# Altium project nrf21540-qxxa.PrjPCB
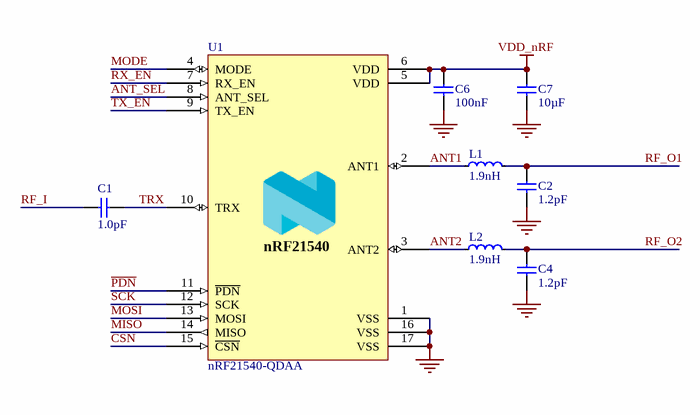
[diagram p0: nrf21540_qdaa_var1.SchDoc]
2 sheets, 18 parts. Net scope: global (net labels, ports and power ports of the same name join across sheets).
Board files: nrf21540_qdaa_var1.PcbDoc, nrf21540_qdaa_var2.PcbDoc
Sheets:
  nrf21540_qdaa_var1.SchDoc
  nrf21540_qdaa_var2.SchDoc

## Sheet nrf21540_qdaa_var1.SchDoc: nRF21540 Reference Layout Alt. 1
size A4; Revision: 0.7; SheetNumber: 1; SheetTotal: 1; DrawnBy: RUBR; DocumentSize: A4; PCAName: nRF21540 Reference Layout Alt. 1

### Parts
(Parts that share a designator on the sheet are numbered #1, #2 ... from top to bottom, then left to right.)
C1#1  1.0pF  [CAPC0603X03L_C]
C2#1  1.2pF  [CAPC0603X03L_C]
C4#1  1.2pF  [CAPC0603X03L_C]
C6#1  100nF  [CAPC0603X03L_C]
C7#1  10µF  [CAPC1608X06L]
L1#1  1.9nH  [INDC0603X03L_C]
L2#1  1.9nH  [INDC0603X03L_C]
U1#1  nRF21540-QDAA  [QFN65P400X400X65_HS-17N]

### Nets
GND: C2#1.1 C4#1.1 C6#1.1 C7#1.1 U1#1.1(VSS) U1#1.16(VSS) U1#1.17(VSS)
VDD_nRF: C6#1.2 C7#1.2 U1#1.5(VDD) U1#1.6(VDD)
ANT1: L1#1.1 U1#1.2(ANT1)
ANT2: L2#1.1 U1#1.3(ANT2)
ANT_SEL: U1#1.8(ANT_SEL)
~{CSN}: U1#1.15(~{CSN})
MISO: U1#1.14(MISO)
MODE: U1#1.4(MODE)
MOSI: U1#1.13(MOSI)
~{PDN}: U1#1.11(~{PDN})
RF_I: C1#1.1
RF_O1: C2#1.2 L1#1.2
RF_O2: C4#1.2 L2#1.2
RX_EN: U1#1.7(RX_EN)
SCK: U1#1.12(SCK)
TRX: C1#1.2 U1#1.10(TRX)
TX_EN: U1#1.9(TX_EN)

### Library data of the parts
C1#1 = C0201-1.0p: Capacitor, NP0, ±5%
C2#1 C4#1 = C0201-1.2p: Capacitor, NP0, ±5%
C6#1 = C0201-100n: Capacitor, X7S, ±10%
C7#1 = C0603-10µ: Capacitor, X7S, ±20%
L1#1 L2#1 = L0201-1n0: High frequency chip inductor ±5%; Part Number: L0201-1n9
U1#1 = nRF21540-QDAA: Radio front-end / range extender for 2.4GHz

## Sheet nrf21540_qdaa_var2.SchDoc: nRF21540 Reference Layout Alt. 2
size A4; Revision: 0.7; SheetNumber: 1; SheetTotal: 1; DrawnBy: RUBR; DocumentSize: A4; PCAName: nRF21540 Reference Layout Alt. 2
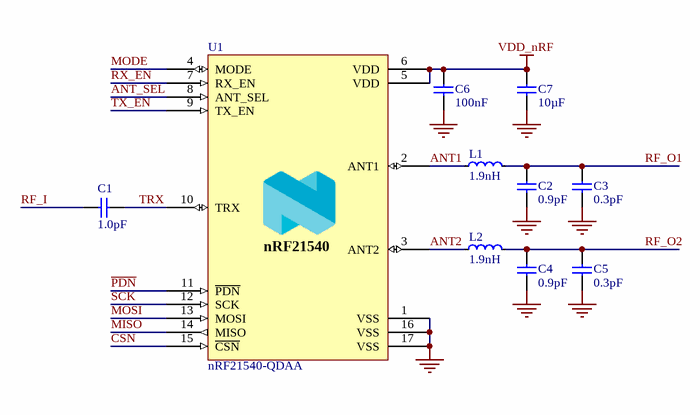
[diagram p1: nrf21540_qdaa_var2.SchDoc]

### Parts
(Parts that share a designator on the sheet are numbered #1, #2 ... from top to bottom, then left to right.)
C1#2  1.0pF  [CAPC0603X03L_C]
C2#2  0.9pF  [CAPC0603X03L_C]
C3  0.3pF  [CAPC0603X03L_C]
C4#2  0.9pF  [CAPC0603X03L_C]
C5  0.3pF  [CAPC0603X03L_C]
C6#2  100nF  [CAPC0603X03L_C]
C7#2  10µF  [CAPC1608X06L]
L1#2  1.9nH  [INDC0603X03L_C]
L2#2  1.9nH  [INDC0603X03L_C]
U1#2  nRF21540-QDAA  [QFN65P400X400X65_HS-17N]

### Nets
GND: C2#2.1 C3.1 C4#2.1 C5.1 C6#2.1 C7#2.1 U1#2.1(VSS) U1#2.16(VSS) U1#2.17(VSS)
VDD_nRF: C6#2.2 C7#2.2 U1#2.5(VDD) U1#2.6(VDD)
ANT1: L1#2.1 U1#2.2(ANT1)
ANT2: L2#2.1 U1#2.3(ANT2)
ANT_SEL: U1#2.8(ANT_SEL)
~{CSN}: U1#2.15(~{CSN})
MISO: U1#2.14(MISO)
MODE: U1#2.4(MODE)
MOSI: U1#2.13(MOSI)
~{PDN}: U1#2.11(~{PDN})
RF_I: C1#2.1
RF_O1: C2#2.2 C3.2 L1#2.2
RF_O2: C4#2.2 C5.2 L2#2.2
RX_EN: U1#2.7(RX_EN)
SCK: U1#2.12(SCK)
TRX: C1#2.2 U1#2.10(TRX)
TX_EN: U1#2.9(TX_EN)

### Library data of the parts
C1#2 = C0201-1.0p: Capacitor, NP0, ±5%
C2#2 C4#2 = C0201-0.9p: Capacitor, NP0, ±5%
C3 C5 = C0201-0.3p: Capacitor, NP0, ±5%
C6#2 = C0201-100n: Capacitor, X7S, ±10%
C7#2 = C0603-10µ: Capacitor, X7S, ±20%
L1#2 L2#2 = L0201-1n0: as L1#1 on sheet nrf21540_qdaa_var1
U1#2 = nRF21540-QDAA: as U1#1 on sheet nrf21540_qdaa_var1

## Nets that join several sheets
GND: nrf21540_qdaa_var1 (7 pins), nrf21540_qdaa_var2 (9 pins)
VDD_nRF: nrf21540_qdaa_var1 (C6#1.2 C7#1.2 U1#1.5 U1#1.6), nrf21540_qdaa_var2 (C6#2.2 C7#2.2 U1#2.5 U1#2.6)
ANT1: nrf21540_qdaa_var1 (L1#1.1 U1#1.2), nrf21540_qdaa_var2 (L1#2.1 U1#2.2)
ANT2: nrf21540_qdaa_var1 (L2#1.1 U1#1.3), nrf21540_qdaa_var2 (L2#2.1 U1#2.3)
ANT_SEL: nrf21540_qdaa_var1 (U1#1.8), nrf21540_qdaa_var2 (U1#2.8)
~{CSN}: nrf21540_qdaa_var1 (U1#1.15), nrf21540_qdaa_var2 (U1#2.15)
MISO: nrf21540_qdaa_var1 (U1#1.14), nrf21540_qdaa_var2 (U1#2.14)
MODE: nrf21540_qdaa_var1 (U1#1.4), nrf21540_qdaa_var2 (U1#2.4)
MOSI: nrf21540_qdaa_var1 (U1#1.13), nrf21540_qdaa_var2 (U1#2.13)
~{PDN}: nrf21540_qdaa_var1 (U1#1.11), nrf21540_qdaa_var2 (U1#2.11)
RF_I: nrf21540_qdaa_var1 (C1#1.1), nrf21540_qdaa_var2 (C1#2.1)
RF_O1: nrf21540_qdaa_var1 (C2#1.2 L1#1.2), nrf21540_qdaa_var2 (C2#2.2 C3.2 L1#2.2)
RF_O2: nrf21540_qdaa_var1 (C4#1.2 L2#1.2), nrf21540_qdaa_var2 (C4#2.2 C5.2 L2#2.2)
RX_EN: nrf21540_qdaa_var1 (U1#1.7), nrf21540_qdaa_var2 (U1#2.7)
SCK: nrf21540_qdaa_var1 (U1#1.12), nrf21540_qdaa_var2 (U1#2.12)
TRX: nrf21540_qdaa_var1 (C1#1.2 U1#1.10), nrf21540_qdaa_var2 (C1#2.2 U1#2.10)
TX_EN: nrf21540_qdaa_var1 (U1#1.9), nrf21540_qdaa_var2 (U1#2.9)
